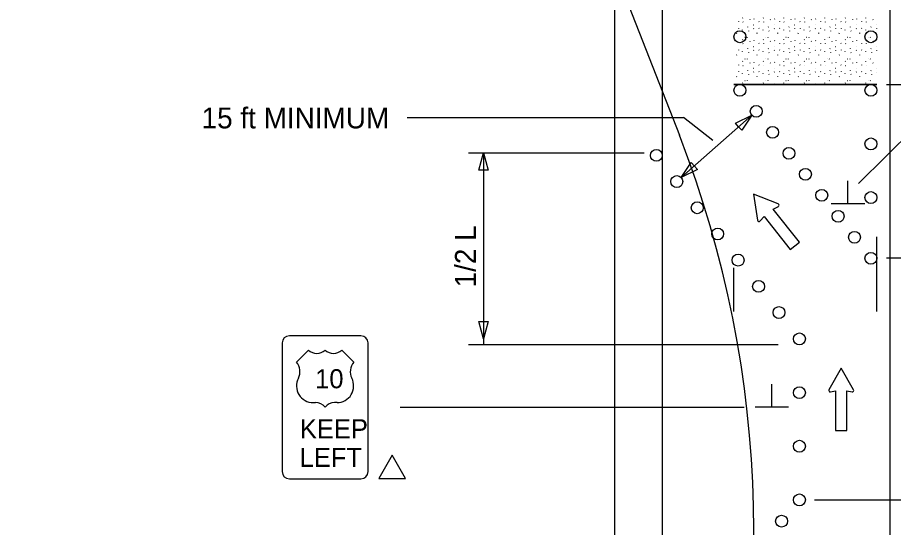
# Model space of a CAD drawing. Extents: x 16630 to 19509, y 5576 to 6998.
# Drawn here: x 16688.1 to 16981.9, y 6297.8 to 6469 of the extents above; entities that cross this region are included whole.
import ezdxf

# ---------------------------------------------------------------- set-up
doc = ezdxf.new("R2010")
doc.units = 0
for name, color, linetype in [('ALI_LEGAL_EX', 7, 'Continuous'), ('MT_SCRATCH_LEVEL_A', 7, 'Continuous'), ('MT_SCRATCH_LEVEL_E', 7, 'Continuous'), ('PAVT_EDGE_EX', 7, 'Continuous'), ('TRAFFIC_SIGNS_PR', 7, 'Continuous'), ('TYPICAL_EX', 7, 'Continuous'), ('TYPICAL_TEXT_DIMEN_PR', 7, 'Continuous')]:
    doc.layers.add(name, color=color, linetype=linetype)

msp = doc.modelspace()

# ---------------------------------------------------------------- linework, layer by layer
at = {"layer": 'ALI_LEGAL_EX'}
for p, q in [((16688.08, 6997.81), (16910.11, 6429.44)), ((16980.68, 6974.12), (16980.68, 6155.98)), ((16980.68, 6922.21), (16980.68, 6058.3))]:
    msp.add_line(p, q, dxfattribs=at)
for points in [[(16976.4, 6370.33), (16976.4, 6395.33)], [(16928.4, 6370.33), (16928.4, 6384.97)]]:
    msp.add_lwpolyline(points, dxfattribs=at)
msp.add_arc((16571.06, 6296.99), 364, 341.1474, 21.3382, dxfattribs=at)
at = {"layer": 'MT_SCRATCH_LEVEL_A'}
for p, q in [((16931.35, 6468.75), (16931.4, 6468.87)), ((16933.72, 6468.3), (16933.77, 6468.23)), ((16935.17, 6468.45), (16935.22, 6468.57)), ((16938.24, 6468.75), (16938.29, 6468.87)), ((16940.6, 6468.3), (16940.66, 6468.23)), ((16942.05, 6468.45), (16942.1, 6468.57)), ((16945.12, 6468.75), (16945.17, 6468.87)), ((16947.49, 6468.3), (16947.54, 6468.23)), ((16948.94, 6468.45), (16948.99, 6468.57)), ((16952.01, 6468.75), (16952.06, 6468.87)), ((16954.38, 6468.3), (16954.43, 6468.23)), ((16955.83, 6468.45), (16955.88, 6468.57)), ((16958.9, 6468.75), (16958.95, 6468.87)), ((16961.27, 6468.3), (16961.32, 6468.23)), ((16962.72, 6468.45), (16962.77, 6468.57)), ((16965.78, 6468.75), (16965.84, 6468.87)), ((16968.15, 6468.3), (16968.21, 6468.23)), ((16969.6, 6468.45), (16969.65, 6468.57)), ((16972.67, 6468.75), (16972.72, 6468.87)), ((16975.04, 6468.3), (16975.09, 6468.23)), ((16929.9, 6467.62), (16929.95, 6467.55)), ((16929.95, 6465.42), (16930, 6465.34)), ((16931.43, 6467.49), (16931.48, 6467.41)), ((16933.07, 6465.7), (16933.12, 6465.81)), ((16934.99, 6466.57), (16935.05, 6466.49)), ((16935.04, 6465.16), (16935.09, 6465.28)), ((16936.78, 6467.62), (16936.84, 6467.55)), ((16936.83, 6465.42), (16936.89, 6465.34)), ((16938.31, 6467.49), (16938.37, 6467.41)), ((16939.96, 6465.7), (16940.01, 6465.81)), ((16941.88, 6466.57), (16941.93, 6466.49)), ((16941.92, 6465.16), (16941.98, 6465.28)), ((16943.67, 6467.62), (16943.72, 6467.55)), ((16943.72, 6465.42), (16943.77, 6465.34)), ((16945.2, 6467.49), (16945.25, 6467.41)), ((16946.84, 6465.7), (16946.9, 6465.81)), ((16948.77, 6466.57), (16948.82, 6466.49)), ((16948.81, 6465.16), (16948.86, 6465.28)), ((16950.56, 6467.62), (16950.61, 6467.55)), ((16950.61, 6465.42), (16950.66, 6465.34)), ((16952.09, 6467.49), (16952.14, 6467.41)), ((16953.73, 6465.7), (16953.78, 6465.81)), ((16955.66, 6466.57), (16955.71, 6466.49)), ((16955.7, 6465.16), (16955.75, 6465.28)), ((16957.45, 6467.62), (16957.5, 6467.55)), ((16957.5, 6465.42), (16957.55, 6465.34)), ((16958.98, 6467.49), (16959.03, 6467.41)), ((16960.62, 6465.7), (16960.67, 6465.81)), ((16962.54, 6466.57), (16962.6, 6466.49)), ((16962.59, 6465.16), (16962.64, 6465.28)), ((16964.33, 6467.62), (16964.39, 6467.55)), ((16964.38, 6465.42), (16964.44, 6465.34)), ((16965.87, 6467.49), (16965.92, 6467.41)), ((16967.51, 6465.7), (16967.56, 6465.81)), ((16969.43, 6466.57), (16969.48, 6466.49)), ((16969.47, 6465.16), (16969.53, 6465.28)), ((16971.22, 6467.62), (16971.27, 6467.55)), ((16971.27, 6465.42), (16971.32, 6465.34)), ((16972.75, 6467.49), (16972.8, 6467.41)), ((16974.39, 6465.7), (16974.45, 6465.81)), ((16976.32, 6466.57), (16976.37, 6466.49)), ((16976.36, 6465.16), (16976.4, 6465.25)), ((16929.33, 6463.66), (16929.38, 6463.78)), ((16931.23, 6464.84), (16931.24, 6464.72)), ((16932.11, 6462.43), (16932.16, 6462.35)), ((16932.85, 6462.4), (16932.9, 6462.32)), ((16933.26, 6464.5), (16933.31, 6464.42)), ((16936.22, 6463.66), (16936.27, 6463.78)), ((16938.12, 6464.84), (16938.13, 6464.72)), ((16939, 6462.43), (16939.05, 6462.35)), ((16939.74, 6462.4), (16939.79, 6462.32)), ((16940.15, 6464.5), (16940.2, 6464.42)), ((16943.1, 6463.66), (16943.15, 6463.78)), ((16945, 6464.84), (16945.01, 6464.72)), ((16945.89, 6462.43), (16945.94, 6462.35)), ((16946.62, 6462.4), (16946.67, 6462.32)), ((16947.03, 6464.5), (16947.08, 6464.42)), ((16949.99, 6463.66), (16950.04, 6463.78)), ((16951.89, 6464.84), (16951.9, 6464.72)), ((16952.77, 6462.43), (16952.83, 6462.35)), ((16953.51, 6462.4), (16953.56, 6462.32)), ((16953.92, 6464.5), (16953.97, 6464.42)), ((16956.88, 6463.66), (16956.93, 6463.78)), ((16958.78, 6464.84), (16958.79, 6464.72)), ((16959.66, 6462.43), (16959.71, 6462.35)), ((16960.4, 6462.4), (16960.45, 6462.32)), ((16960.81, 6464.5), (16960.86, 6464.42)), ((16963.76, 6463.66), (16963.82, 6463.78)), ((16965.67, 6464.84), (16965.68, 6464.72)), ((16966.55, 6462.43), (16966.6, 6462.35)), ((16967.29, 6462.4), (16967.34, 6462.32)), ((16967.69, 6464.5), (16967.75, 6464.42)), ((16970.65, 6463.66), (16970.7, 6463.78)), ((16972.55, 6464.84), (16972.56, 6464.72)), ((16973.44, 6462.43), (16973.49, 6462.35)), ((16974.17, 6462.4), (16974.22, 6462.32)), ((16974.58, 6464.5), (16974.63, 6464.42)), ((16931.35, 6461.47), (16931.4, 6461.58)), ((16931.43, 6460.2), (16931.48, 6460.12)), ((16933.72, 6461.02), (16933.77, 6460.94)), ((16935.17, 6461.17), (16935.22, 6461.28)), ((16936.78, 6460.34), (16936.84, 6460.26)), ((16938.24, 6461.47), (16938.29, 6461.58)), ((16938.31, 6460.2), (16938.37, 6460.12)), ((16940.6, 6461.02), (16940.66, 6460.94)), ((16942.05, 6461.17), (16942.1, 6461.28)), ((16943.67, 6460.34), (16943.72, 6460.26)), ((16945.12, 6461.47), (16945.17, 6461.58)), ((16945.2, 6460.2), (16945.25, 6460.12)), ((16947.49, 6461.02), (16947.54, 6460.94)), ((16948.94, 6461.17), (16948.99, 6461.28)), ((16950.56, 6460.34), (16950.61, 6460.26)), ((16952.01, 6461.47), (16952.06, 6461.58)), ((16952.09, 6460.2), (16952.14, 6460.12)), ((16954.38, 6461.02), (16954.43, 6460.94)), ((16955.83, 6461.17), (16955.88, 6461.28)), ((16957.45, 6460.34), (16957.5, 6460.26)), ((16958.9, 6461.47), (16958.95, 6461.58)), ((16958.98, 6460.2), (16959.03, 6460.12)), ((16961.27, 6461.02), (16961.32, 6460.94)), ((16962.72, 6461.17), (16962.77, 6461.28)), ((16964.33, 6460.34), (16964.39, 6460.26)), ((16965.78, 6461.47), (16965.84, 6461.58)), ((16965.87, 6460.2), (16965.92, 6460.12)), ((16968.15, 6461.02), (16968.21, 6460.94)), ((16969.6, 6461.17), (16969.65, 6461.28)), ((16971.22, 6460.34), (16971.27, 6460.26)), ((16972.67, 6461.47), (16972.72, 6461.58)), ((16972.75, 6460.2), (16972.8, 6460.12)), ((16975.04, 6461.02), (16975.09, 6460.94)), ((16929.33, 6456.38), (16929.38, 6456.49)), ((16929.95, 6458.13), (16930, 6458.05)), ((16931.23, 6457.56), (16931.24, 6457.44)), ((16933.07, 6458.41), (16933.12, 6458.53)), ((16933.26, 6457.21), (16933.31, 6457.13)), ((16934.99, 6459.28), (16935.05, 6459.2)), ((16935.04, 6457.88), (16935.09, 6458)), ((16936.22, 6456.38), (16936.27, 6456.49)), ((16936.83, 6458.13), (16936.89, 6458.05)), ((16938.12, 6457.56), (16938.13, 6457.44)), ((16939.96, 6458.41), (16940.01, 6458.53)), ((16940.15, 6457.21), (16940.2, 6457.13)), ((16941.88, 6459.28), (16941.93, 6459.2)), ((16941.92, 6457.88), (16941.98, 6458)), ((16943.1, 6456.38), (16943.15, 6456.49)), ((16943.72, 6458.13), (16943.77, 6458.05)), ((16945, 6457.56), (16945.01, 6457.44)), ((16946.84, 6458.41), (16946.9, 6458.53)), ((16947.03, 6457.21), (16947.08, 6457.13)), ((16948.77, 6459.28), (16948.82, 6459.2)), ((16948.81, 6457.88), (16948.86, 6458)), ((16949.99, 6456.38), (16950.04, 6456.49)), ((16950.61, 6458.13), (16950.66, 6458.05)), ((16951.89, 6457.56), (16951.9, 6457.44)), ((16953.73, 6458.41), (16953.78, 6458.53)), ((16953.92, 6457.21), (16953.97, 6457.13)), ((16955.66, 6459.28), (16955.71, 6459.2)), ((16955.7, 6457.88), (16955.75, 6458)), ((16956.88, 6456.38), (16956.93, 6456.49)), ((16957.5, 6458.13), (16957.55, 6458.05)), ((16958.78, 6457.56), (16958.79, 6457.44)), ((16960.62, 6458.41), (16960.67, 6458.53)), ((16960.81, 6457.21), (16960.86, 6457.13)), ((16962.54, 6459.28), (16962.6, 6459.2)), ((16962.59, 6457.88), (16962.64, 6458)), ((16963.76, 6456.38), (16963.82, 6456.49)), ((16964.38, 6458.13), (16964.44, 6458.05)), ((16965.67, 6457.56), (16965.68, 6457.44)), ((16967.51, 6458.41), (16967.56, 6458.53)), ((16967.69, 6457.21), (16967.75, 6457.13)), ((16969.43, 6459.28), (16969.48, 6459.2)), ((16969.47, 6457.88), (16969.53, 6458)), ((16970.65, 6456.38), (16970.7, 6456.49)), ((16971.27, 6458.13), (16971.32, 6458.05)), ((16972.55, 6457.56), (16972.56, 6457.44)), ((16974.39, 6458.41), (16974.45, 6458.53)), ((16974.58, 6457.21), (16974.63, 6457.13)), ((16976.32, 6459.28), (16976.37, 6459.2)), ((16976.36, 6457.88), (16976.4, 6457.97)), ((16931.35, 6454.18), (16931.4, 6454.3)), ((16932.11, 6455.14), (16932.16, 6455.06)), ((16932.85, 6455.11), (16932.9, 6455.03)), ((16933.72, 6453.73), (16933.77, 6453.65)), ((16935.17, 6453.88), (16935.22, 6454)), ((16938.24, 6454.18), (16938.29, 6454.3)), ((16939, 6455.14), (16939.05, 6455.06)), ((16939.74, 6455.11), (16939.79, 6455.03)), ((16940.6, 6453.73), (16940.66, 6453.65)), ((16942.05, 6453.88), (16942.1, 6454)), ((16945.12, 6454.18), (16945.17, 6454.3)), ((16945.89, 6455.14), (16945.94, 6455.06)), ((16946.62, 6455.11), (16946.67, 6455.03)), ((16947.49, 6453.73), (16947.54, 6453.65)), ((16948.94, 6453.88), (16948.99, 6454)), ((16952.01, 6454.18), (16952.06, 6454.3)), ((16952.77, 6455.14), (16952.83, 6455.06)), ((16953.51, 6455.11), (16953.56, 6455.03)), ((16954.38, 6453.73), (16954.43, 6453.65)), ((16955.83, 6453.88), (16955.88, 6454)), ((16958.9, 6454.18), (16958.95, 6454.3)), ((16959.66, 6455.14), (16959.71, 6455.06)), ((16960.4, 6455.11), (16960.45, 6455.03)), ((16961.27, 6453.73), (16961.32, 6453.65)), ((16962.72, 6453.88), (16962.77, 6454)), ((16965.78, 6454.18), (16965.84, 6454.3)), ((16966.55, 6455.14), (16966.6, 6455.06)), ((16967.29, 6455.11), (16967.34, 6455.03)), ((16968.15, 6453.73), (16968.21, 6453.65)), ((16969.6, 6453.88), (16969.65, 6454)), ((16972.67, 6454.18), (16972.72, 6454.3)), ((16973.44, 6455.14), (16973.49, 6455.06)), ((16974.17, 6455.11), (16974.22, 6455.03)), ((16975.04, 6453.73), (16975.09, 6453.65)), ((16929.9, 6453.06), (16929.95, 6452.98)), ((16929.95, 6450.85), (16930, 6450.77)), ((16931.43, 6452.91), (16931.48, 6452.84)), ((16933.07, 6451.13), (16933.12, 6451.24)), ((16934.99, 6452), (16935.05, 6451.92)), ((16935.04, 6450.6), (16935.09, 6450.71)), ((16936.78, 6453.06), (16936.84, 6452.98)), ((16936.83, 6450.85), (16936.89, 6450.77)), ((16938.31, 6452.91), (16938.37, 6452.84)), ((16939.96, 6451.13), (16940.01, 6451.24)), ((16941.88, 6452), (16941.93, 6451.92)), ((16941.92, 6450.6), (16941.98, 6450.71)), ((16943.67, 6453.06), (16943.72, 6452.98)), ((16943.72, 6450.85), (16943.77, 6450.77)), ((16945.2, 6452.91), (16945.25, 6452.84)), ((16946.84, 6451.13), (16946.9, 6451.24)), ((16948.77, 6452), (16948.82, 6451.92)), ((16948.81, 6450.6), (16948.86, 6450.71)), ((16950.56, 6453.06), (16950.61, 6452.98)), ((16950.61, 6450.85), (16950.66, 6450.77)), ((16952.09, 6452.91), (16952.14, 6452.84)), ((16953.73, 6451.13), (16953.78, 6451.24)), ((16955.66, 6452), (16955.71, 6451.92)), ((16955.7, 6450.6), (16955.75, 6450.71)), ((16957.45, 6453.06), (16957.5, 6452.98)), ((16957.5, 6450.85), (16957.55, 6450.77)), ((16958.98, 6452.91), (16959.03, 6452.84)), ((16960.62, 6451.13), (16960.67, 6451.24)), ((16962.54, 6452), (16962.6, 6451.92)), ((16962.59, 6450.6), (16962.64, 6450.71)), ((16964.33, 6453.06), (16964.39, 6452.98)), ((16964.38, 6450.85), (16964.44, 6450.77)), ((16965.87, 6452.91), (16965.92, 6452.84)), ((16967.51, 6451.13), (16967.56, 6451.24)), ((16969.43, 6452), (16969.48, 6451.92)), ((16969.47, 6450.6), (16969.53, 6450.71)), ((16971.22, 6453.06), (16971.27, 6452.98)), ((16971.27, 6450.85), (16971.32, 6450.77)), ((16972.75, 6452.91), (16972.8, 6452.84)), ((16974.39, 6451.13), (16974.45, 6451.24)), ((16976.32, 6452), (16976.37, 6451.92)), ((16976.36, 6450.6), (16976.4, 6450.68)), ((16929.33, 6449.09), (16929.38, 6449.21)), ((16931.23, 6450.27), (16931.24, 6450.15)), ((16932.11, 6447.86), (16932.16, 6447.78)), ((16932.85, 6447.83), (16932.9, 6447.75)), ((16933.26, 6449.93), (16933.31, 6449.85)), ((16936.22, 6449.09), (16936.27, 6449.21)), ((16938.12, 6450.27), (16938.13, 6450.15)), ((16939, 6447.86), (16939.05, 6447.78)), ((16939.74, 6447.83), (16939.79, 6447.75)), ((16940.15, 6449.93), (16940.2, 6449.85)), ((16943.1, 6449.09), (16943.15, 6449.21)), ((16945, 6450.27), (16945.01, 6450.15)), ((16945.89, 6447.86), (16945.94, 6447.78)), ((16946.62, 6447.83), (16946.67, 6447.75)), ((16947.03, 6449.93), (16947.08, 6449.85)), ((16949.99, 6449.09), (16950.04, 6449.21)), ((16951.89, 6450.27), (16951.9, 6450.15)), ((16952.77, 6447.86), (16952.83, 6447.78)), ((16953.51, 6447.83), (16953.56, 6447.75)), ((16953.92, 6449.93), (16953.97, 6449.85)), ((16956.88, 6449.09), (16956.93, 6449.21)), ((16958.78, 6450.27), (16958.79, 6450.15)), ((16959.66, 6447.86), (16959.71, 6447.78)), ((16960.4, 6447.83), (16960.45, 6447.75)), ((16960.81, 6449.93), (16960.86, 6449.85)), ((16963.76, 6449.09), (16963.82, 6449.21)), ((16965.67, 6450.27), (16965.68, 6450.15)), ((16966.55, 6447.86), (16966.6, 6447.78)), ((16967.29, 6447.83), (16967.34, 6447.75)), ((16967.69, 6449.93), (16967.75, 6449.85)), ((16970.65, 6449.09), (16970.7, 6449.21)), ((16972.55, 6450.27), (16972.56, 6450.15)), ((16973.44, 6447.86), (16973.49, 6447.78)), ((16974.17, 6447.83), (16974.22, 6447.75)), ((16974.58, 6449.93), (16974.63, 6449.85)), ((16976.4, 6446.53), (16928.4, 6446.53)), ((16928.4, 6446.53), (16976.4, 6446.53)), ((16931.35, 6446.9), (16931.4, 6447.01)), ((16935.17, 6446.6), (16935.22, 6446.72)), ((16938.24, 6446.9), (16938.29, 6447.01)), ((16942.05, 6446.6), (16942.1, 6446.72)), ((16945.12, 6446.9), (16945.17, 6447.01)), ((16948.94, 6446.6), (16948.99, 6446.72)), ((16952.01, 6446.9), (16952.06, 6447.01)), ((16955.83, 6446.6), (16955.88, 6446.72)), ((16958.9, 6446.9), (16958.95, 6447.01)), ((16962.72, 6446.6), (16962.77, 6446.72)), ((16965.78, 6446.9), (16965.84, 6447.01)), ((16969.6, 6446.6), (16969.65, 6446.72)), ((16972.67, 6446.9), (16972.72, 6447.01))]:
    msp.add_line(p, q, dxfattribs=at)
at = {"layer": 'MT_SCRATCH_LEVEL_E'}
for p, q in [((16964.4, 6351.23), (16960.29, 6343.99)), ((16968.55, 6343.99), (16964.4, 6351.23)), ((16960.77, 6343.31), (16962.55, 6343.62)), ((16962.55, 6343.62), (16962.55, 6330.36)), ((16966.29, 6330.36), (16966.29, 6343.62)), ((16966.29, 6343.62), (16968.07, 6343.31)), ((16962.55, 6330.36), (16966.29, 6330.36))]:
    msp.add_line(p, q, dxfattribs=at)
for centre, start, end in [((16960.7, 6343.76), 150.4248, 279.9638), ((16968.14, 6343.76), 260.0362, 29.7731)]:
    msp.add_arc(centre, 0.463, start, end, dxfattribs=at)
at = {"layer": 'PAVT_EDGE_EX'}
for p, q in [((16888.4, 6480.53), (16888.4, 6125.9)), ((16904.4, 6480.53), (16904.4, 6125.9))]:
    msp.add_line(p, q, dxfattribs=at)
at = {"layer": 'TRAFFIC_SIGNS_PR'}
for p, q in [((16776.87, 6359.71), (16776.87, 6316.51)), ((16803.27, 6362.11), (16779.27, 6362.11)), ((16805.67, 6316.51), (16805.67, 6359.71)), ((16779.27, 6314.11), (16803.27, 6314.11))]:
    msp.add_line(p, q, dxfattribs=at)
for centre in [(16930.41, 6462.53), (16974.39, 6462.53), (16930.41, 6444.53), (16930.41, 6444.53), (16974.39, 6444.53), (16935.9, 6437.48), (16941.4, 6430.43), (16974.39, 6426.53), (16902.4, 6422.7), (16946.89, 6423.38), (16952.39, 6416.34), (16909.26, 6413.9), (16957.88, 6409.29), (16974.39, 6408.53), (16916.11, 6405.11), (16963.38, 6402.24), (16922.97, 6396.31), (16968.87, 6395.19), (16929.83, 6387.52), (16974.37, 6388.14), (16936.69, 6378.72), (16943.54, 6369.93), (16950.4, 6361.08), (16950.4, 6343.03), (16950.4, 6325.03), (16950.4, 6307.03), (16950.4, 6307.03), (16944.4, 6299.89)]:
    msp.add_circle(centre, 2, dxfattribs=at)
for centre, start, end in [((16779.27, 6359.71), 90, 180), ((16803.27, 6359.71), 0, 90), ((16779.27, 6316.51), 180, 270), ((16803.27, 6316.51), 270, 0)]:
    msp.add_arc(centre, 2.4, start, end, dxfattribs=at)
at = {"layer": 'TYPICAL_EX'}
for p, q in [((16781.67, 6353.31), (16785.67, 6357.31)), ((16800.87, 6353.31), (16796.87, 6357.31)), ((16787.26, 6339.7), (16788.06, 6339.7)), ((16795.27, 6339.7), (16794.47, 6339.7))]:
    msp.add_line(p, q, dxfattribs=at)
for centre, radius, start, end in [((16788.47, 6360.22), 4.04, 226.1404, 313.8596), ((16794.07, 6360.22), 4.04, 226.1404, 313.8596), ((16777.88, 6350.11), 4.96, 333.0977, 40.1936), ((16804.66, 6350.11), 4.96, 139.8064, 206.9023), ((16787.27, 6345.29), 5.59, 152.6698, 269.9013), ((16795.26, 6345.29), 5.59, 270.0987, 27.3302), ((16788.07, 6335.69), 4.01, 37.1038, 90.1385), ((16794.46, 6335.69), 4.01, 89.8615, 142.8962)]:
    msp.add_arc(centre, radius, start, end, dxfattribs=at)
at = {"layer": 'TYPICAL_TEXT_DIMEN_PR'}
for p, q in [((16979.6, 6446.53), (17065.4, 6446.53)), ((16934.4, 6436.16), (16910.76, 6415.23)), ((16928.97, 6433.45), (16934.4, 6436.16)), ((16934.4, 6436.16), (16931.06, 6431.1)), ((16970.24, 6413.2), (16993.65, 6436.53)), ((16818.83, 6435.45), (16911.45, 6435.45)), ((16921.31, 6427.65), (16911.45, 6435.45)), ((16930.01, 6432.27), (16928.97, 6433.45)), ((16931.06, 6431.1), (16930.01, 6432.27)), ((16839.4, 6423.59), (16898.3, 6423.59)), ((16842.83, 6417.73), (16844.4, 6423.59)), ((16844.4, 6423.59), (16844.4, 6359.08)), ((16844.4, 6423.59), (16845.97, 6417.73)), ((16910.76, 6415.23), (16914.1, 6420.29)), ((16914.1, 6420.29), (16915.15, 6419.11)), ((16915.15, 6419.11), (16916.19, 6417.94)), ((16844.4, 6417.73), (16842.83, 6417.73)), ((16845.97, 6417.73), (16844.4, 6417.73)), ((16916.19, 6417.94), (16910.76, 6415.23)), ((16966.68, 6406.41), (16966.68, 6414.19)), ((16943.28, 6406.4), (16935.01, 6409.7)), ((16935.01, 6409.7), (16936.38, 6400.93)), ((16941.64, 6404.6), (16943.33, 6405.51)), ((16950.42, 6393.52), (16941.64, 6404.6)), ((16972.3, 6406.41), (16961.05, 6406.41)), ((16937.23, 6400.68), (16938.51, 6402.12)), ((16938.51, 6402.12), (16947.3, 6391.04)), ((16947.3, 6391.04), (16950.42, 6393.52)), ((17095.19, 6388.14), (16979.6, 6388.14)), ((16844.4, 6361.08), (16842.83, 6366.94)), ((16842.83, 6366.94), (16844.4, 6366.94)), ((16844.4, 6366.94), (16845.97, 6366.94)), ((16845.97, 6366.94), (16844.4, 6361.08)), ((16943.29, 6359.08), (16839.4, 6359.08)), ((16941.15, 6338.14), (16941.15, 6345.93)), ((16816.43, 6338.14), (16931.9, 6338.14)), ((16946.78, 6338.14), (16935.53, 6338.14)), ((16955.45, 6307.03), (17095.19, 6307.03))]:
    msp.add_line(p, q, dxfattribs=at)
msp.add_lwpolyline([(16813.76, 6322.07), (16809.24, 6314.24), (16818.29, 6314.24)], close=True, dxfattribs=at)
for centre, start, end in [((16943.08, 6405.94), 298.4553, 68.1923), ((16936.86, 6401.01), 188.844, 318.3829)]:
    msp.add_arc(centre, 0.494, start, end, dxfattribs=at)

# ---------------------------------------------------------------- texts
at = {"layer": 'TRAFFIC_SIGNS_PR'}
for s, p in [('10', (16787.93, 6344.51)), ('KEEP', (16782.8, 6327.71)), ('LEFT', (16782.72, 6318.11))]:
    msp.add_text(s, height=6.4, dxfattribs=at).set_placement(p)
at = {"layer": 'TYPICAL_TEXT_DIMEN_PR'}
msp.add_text('15 ft MINIMUM', height=7, dxfattribs=at).set_placement((16749.83, 6431.75))
msp.add_text('1/2 L', height=7, rotation=90, dxfattribs=at).set_placement((16841.84, 6378.38))

doc.saveas('drawing.dxf')
